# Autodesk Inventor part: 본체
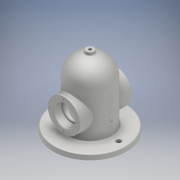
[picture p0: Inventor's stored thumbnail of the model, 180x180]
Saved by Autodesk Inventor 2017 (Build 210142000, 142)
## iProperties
Created: 2019-11
Part Number: 본체
Material: Aluminum 6061
Document SubType Name: Modeling
Designer: 1-00-lg-1
Mass: 1106.12 g
Surface Area: 883.259 cm^2
Volume: 409.674 cm^3
Density: 2.7 g/cm^3
Appearance: Aluminum - Flat
Author: 1-00-lg-1
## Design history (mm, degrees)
sketch "Sketch1"
  geometry: C1 r 70 at (0, 0); 1 further point
  constraints: 1 centre point, 1 coincident
  dimensions: "d0" = 140 diameter of C1
extrude "Extrusion1" new body sketch "Sketch1" distance "d1" = 10; taper "d2" = 0 deg
sketch "Sketch2"
  geometry: C1 r 40 at (0, 0); 1 further point
  constraints: 1 centre point, 1 coincident
  dimensions: "d3" = 80 diameter of C1
extrude "Extrusion2" join sketch "Sketch2" distance "d4" = 80; taper "d5" = 0 deg
sketch "Sketch5"
  geometry: L1 (40, 90)-(-40, 90) reference; L2 (0, 130)-(0, 90); L3 (0, 90)-(-40, 90); A1 r 40 centre (0, 90) between (0, 130) and (-40, 90); 1 further point
  constraints: 5 end point, 2 point on circle, 1 centre point, 1 collinear, 1 midpoint, 1 point on line, 1 vertical
revolve "Revolution1" sketch "Sketch5" stored, may be unused: angle "d7" = 90 deg
sketch "Sketch7"
  geometry: C1 r 30 at (0, 0); 1 further point
  constraints: 1 centre point, 1 coincident
  dimensions: "d8" = 60 diameter of C1
extrude "Extrusion3" cut sketch "Sketch7" distance "d9" = 90; taper "d10" = 0 deg
sketch "Sketch8"
  geometry: L1 (30, 90)-(-30, 90) reference; L2 (0, 120)-(0, 90); L3 (0, 90)-(-30, 90); A1 r 30 centre (0, 90) between (0, 120) and (-30, 90); 1 further point
  constraints: 5 end point, 2 point on circle, 1 centre point, 1 midpoint, 1 perpendicular, 1 vertical
revolve "Revolution2" sketch "Sketch8" stored, may be unused: angle "d12" = 90 deg
workplane "Work Plane1"
sketch "Sketch9"
  geometry: L1 (-70, 0)-(70, 0) reference; C1 r 31 at (0, 50); 1 further point
  constraints: 1 centre point, 1 vertical alignment
  dimensions: "d14" = 62 diameter of C1; "d15" = 50 distance from line of L1 C1.centre
extrude "Extrusion4" join sketch "Sketch9" stored distance "d16" = 90; taper "d17" = 0 deg
sketch "Sketch10" dims "d18" = 52
  geometry: 3 further points
  constraints: 1 vertical alignment, 2 other
hole "Hole1" sketch "Sketch10" at (0, 26) diameter "d19" = 3.242; stored, may be unused: countersink angle "d23" = 90 deg, drill point angle "d25" = 118 deg; dims "d20" = 8, "d21" = 4, "d22" = 2, "d24" = 10
pattern_circular "Circular Pattern1" dims angle "d27" = 360 deg
sketch "Sketch11"
  geometry: C1 r 20 at (0, 0); 1 further point
  constraints: 1 centre point
  dimensions: "d29" = 40 diameter of C1
extrude "Extrusion5" cut sketch "Sketch11" distance "d30" = 15; taper "d31" = 0 deg
sketch "Sketch12"
  geometry: C1 r 16.5 at (0, 0); 1 further point
  constraints: 1 centre point
  dimensions: "d32" = 33 diameter of C1
extrude "Extrusion6" cut sketch "Sketch12" stored distance "d33" = 15; taper "d34" = 0 deg
mirror "Mirror1"
workplane "Work Plane2"
sketch "Sketch13"
  geometry: C1 r 7.5 at (0, 0); 1 further point
  constraints: 1 centre point, 1 coincident
  dimensions: "d36" = 15 diameter of C1
extrude "Extrusion7" join sketch "Sketch13" stored distance "d37" = 15; taper "d38" = 0 deg
sketch "Sketch14"
  geometry: 2 further points
  constraints: 1 coincident
hole "Hole2" sketch "Sketch14" at (0, 0) diameter "d39" = 5.188; stored, may be unused: countersink angle "d43" = 90 deg, drill point angle "d45" = 118 deg; dims "d40" = 12, "d41" = 4, "d42" = 2, "d44" = 16
sketch "Sketch15"
  geometry: C1 r 2.594 at (0, 0) reference; C2 r 4.5 at (-55, 0); C3 r 4.5 at (55, 0); A1 r 55 centre (0, 0) between (-55, 0) and (55, 0); 1 further point
  constraints: 3 centre point, 2 point on circle, 1 coincident, 1 equal radius
  dimensions: "d46" = 110 diameter of A1; "d47" = 9 diameter of C2
extrude "Extrusion8" cut sketch "Sketch15" stored distance "d48" = 15; taper "d49" = 0 deg
workplane "Work Plane3"
sketch "Sketch16"
  geometry: L1 (0, 25)-(0, 75); L2 (-70, 0)-(70, 0) reference; L3 (-7.307, 72.457)-(7.307, 72.457); 3 further points
  constraints: 4 end point, 2 horizontal, 2 midpoint, 1 point on line, 1 vertical
  dimensions: "d51" = 50 distance from line of L2 point (0, 50); "d52" = 50 distance of L1.start L1.end
emboss "Emboss1" sketch "Sketch16" dims "d1" = 10, "d2" = 0, "d9" = 90, "d10" = 0, "d53" = 0.5, "d54" = 0
fillet "Fillet1" dims "d55" = 0.3
fillet "Fillet2" dims "d56" = 3
chamfer "Chamfer1" distance "d57" = 1; stored, may be unused: second distance "d58" = 2, angle "d59" = 45 deg
body "Solid1"
other parameters: "d35" = -135
